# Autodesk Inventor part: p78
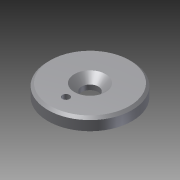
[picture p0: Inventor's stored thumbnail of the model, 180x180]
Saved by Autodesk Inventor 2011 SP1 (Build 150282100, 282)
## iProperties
Created: 2014-02
Part Number: p78
Document SubType Name: Modeling
Designer: Administrator
Density: 1 g/cm^3
Author: Administrator
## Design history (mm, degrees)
sketch "草图1"
  geometry: C1 r 17.5 at (0, 0); 1 further point
  constraints: 1 centre point, 1 coincident
  dimensions: "d0" = 35 diameter of C1
extrude "拉伸1" new body sketch "草图1" distance "d1" = 5; taper "d2" = 0 deg
hole "Hole1" diameter "d5" = 7; stored, may be unused: countersink angle "d9" = 90 deg, drill point angle "d11" = 0 deg; dims "d3" = 10, "d4" = 10, "d6" = 6, "d7" = 13, "d8" = 2, "d10" = 8
sketch "草图2" dims "d12" = 20
  geometry: C1 r 17.5 at (0, 0) reference; 2 further points
  constraints: 1 coincident, 1 vertical alignment, 2 other
hole "Hole2" sketch "草图2" at (0, -10) diameter "d13" = 3; stored, may be unused: countersink angle "d17" = 90 deg, drill point angle "d19" = 90 deg; dims "d14" = 6, "d15" = 13, "d16" = 2, "d18" = 8
chamfer "倒角1" distance "d20" = 1; stored, may be unused: second distance "d21" = 2, angle "d22" = 45 deg
node "实体1"
